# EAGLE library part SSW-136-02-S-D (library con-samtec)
THROUGH-HOLE .025" SQ POST SOCKET Source: Samtec SSW.pdf
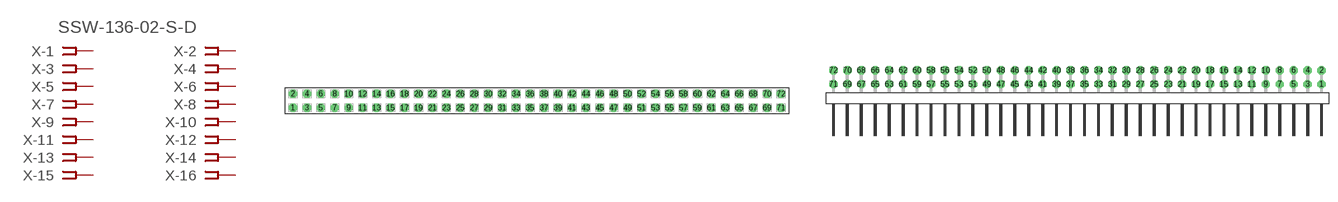
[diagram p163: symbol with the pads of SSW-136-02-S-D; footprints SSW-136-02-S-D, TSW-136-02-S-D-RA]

Designator prefix X; gates -1=FPINV -2=FPIN -3=FPIN -4=FPIN -5=FPIN -6=FPIN -7=FPIN -8=FPIN -9=FPIN -10=FPIN -11=FPIN -12=FPIN -13=FPIN -14=FPIN -15=FPIN -16=FPIN -17=FPIN -18=FPIN -19=FPIN -20=FPIN -21=FPIN -22=FPIN -23=FPIN -24=FPIN -25=FPIN -26=FPIN -27=FPIN -28=FPIN -29=FPIN -30=FPIN -31=FPIN -32=FPIN -33=FPIN -34=FPIN -35=FPIN -36=FPIN -37=FPIN -38=FPIN -39=FPIN -40=FPIN -41=FPIN -42=FPIN -43=FPIN -44=FPIN -45=FPIN -46=FPIN -47=FPIN -48=FPIN -49=FPIN -50=FPIN -51=FPIN -52=FPIN -53=FPIN -54=FPIN -55=FPIN -56=FPIN -57=FPIN -58=FPIN -59=FPIN -60=FPIN -61=FPIN -62=FPIN -63=FPIN -64=FPIN -65=FPIN -66=FPIN -67=FPIN -68=FPIN -69=FPIN -70=FPIN -71=FPIN -72=FPIN

## SSW-136-02-S-D (MPN: SSW-136-02-S-D; OC_FARNELL: unknown; OC_NEWARK: 11P9902)  [SSW-136-02-S-D]
1  -1:1  pas
2  -2:1  pas
3  -3:1  pas
4  -4:1  pas
5  -5:1  pas
6  -6:1  pas
7  -7:1  pas
8  -8:1  pas
9  -9:1  pas
10  -10:1  pas
11  -11:1  pas
12  -12:1  pas
13  -13:1  pas
14  -14:1  pas
15  -15:1  pas
16  -16:1  pas
17  -17:1  pas
18  -18:1  pas
19  -19:1  pas
20  -20:1  pas
21  -21:1  pas
22  -22:1  pas
23  -23:1  pas
24  -24:1  pas
25  -25:1  pas
26  -26:1  pas
27  -27:1  pas
28  -28:1  pas
29  -29:1  pas
30  -30:1  pas
31  -31:1  pas
32  -32:1  pas
33  -33:1  pas
34  -34:1  pas
35  -35:1  pas
36  -36:1  pas
37  -37:1  pas
38  -38:1  pas
39  -39:1  pas
40  -40:1  pas
41  -41:1  pas
42  -42:1  pas
43  -43:1  pas
44  -44:1  pas
45  -45:1  pas
46  -46:1  pas
47  -47:1  pas
48  -48:1  pas
49  -49:1  pas
50  -50:1  pas
51  -51:1  pas
52  -52:1  pas
53  -53:1  pas
54  -54:1  pas
55  -55:1  pas
56  -56:1  pas
57  -57:1  pas
58  -58:1  pas
59  -59:1  pas
60  -60:1  pas
61  -61:1  pas
62  -62:1  pas
63  -63:1  pas
64  -64:1  pas
65  -65:1  pas
66  -66:1  pas
67  -67:1  pas
68  -68:1  pas
69  -69:1  pas
70  -70:1  pas
71  -71:1  pas
72  -72:1  pas

## SSW-136-02-S-D-RA (MPN: SSW-136-02-S-D-RA; OC_FARNELL: unknown; OC_NEWARK: 11P9903)  [TSW-136-02-S-D-RA]
Pads as for SSW-136-02-S-D

## Footprint SSW-136-02-S-D (pad centres in mm)
THROUGH-HOLE .025" SQ POST SOCKET Source: Samtec SSW.pdf
drill 1 pad 1.5 octagon: 1 -44.45,-1.27; 2 -44.45,1.27; 3 -41.91,-1.27; 4 -41.91,1.27; 5 -39.37,-1.27; 6 -39.37,1.27; 7 -36.83,-1.27; 8 -36.83,1.27; 9 -34.29,-1.27; 10 -34.29,1.27; 11 -31.75,-1.27; 12 -31.75,1.27; 13 -29.21,-1.27; 14 -29.21,1.27; 15 -26.67,-1.27; 16 -26.67,1.27; 17 -24.13,-1.27; 18 -24.13,1.27; 19 -21.59,-1.27; 20 -21.59,1.27; 21 -19.05,-1.27; 22 -19.05,1.27; 23 -16.51,-1.27; 24 -16.51,1.27; 25 -13.97,-1.27; 26 -13.97,1.27; 27 -11.43,-1.27; 28 -11.43,1.27; 29 -8.89,-1.27; 30 -8.89,1.27; 31 -6.35,-1.27; 32 -6.35,1.27; 33 -3.81,-1.27; 34 -3.81,1.27; 35 -1.27,-1.27; 36 -1.27,1.27; 37 1.27,-1.27; 38 1.27,1.27; 39 3.81,-1.27; 40 3.81,1.27; 41 6.35,-1.27; 42 6.35,1.27; 43 8.89,-1.27; 44 8.89,1.27; 45 11.43,-1.27; 46 11.43,1.27; 47 13.97,-1.27; 48 13.97,1.27; 49 16.51,-1.27; 50 16.51,1.27; 51 19.05,-1.27; 52 19.05,1.27; 53 21.59,-1.27; 54 21.59,1.27; 55 24.13,-1.27; 56 24.13,1.27; 57 26.67,-1.27; 58 26.67,1.27; 59 29.21,-1.27; 60 29.21,1.27; 61 31.75,-1.27; 62 31.75,1.27; 63 34.29,-1.27; 64 34.29,1.27; 65 36.83,-1.27; 66 36.83,1.27; 67 39.37,-1.27; 68 39.37,1.27; 69 41.91,-1.27; 70 41.91,1.27; 71 44.45,-1.27; 72 44.45,1.27

## Footprint TSW-136-02-S-D-RA (pad centres in mm)
THROUGH-HOLE .025" SQ POST HEADER Source: Samtec TSW.pdf
drill 1 pad 1.5 octagon: 1 44.45,1.524; 2 44.45,4.064; 3 41.91,1.524; 4 41.91,4.064; 5 39.37,1.524; 6 39.37,4.064; 7 36.83,1.524; 8 36.83,4.064; 9 34.29,1.524; 10 34.29,4.064; 11 31.75,1.524; 12 31.75,4.064; 13 29.21,1.524; 14 29.21,4.064; 15 26.67,1.524; 16 26.67,4.064; 17 24.13,1.524; 18 24.13,4.064; 19 21.59,1.524; 20 21.59,4.064; 21 19.05,1.524; 22 19.05,4.064; 23 16.51,1.524; 24 16.51,4.064; 25 13.97,1.524; 26 13.97,4.064; 27 11.43,1.524; 28 11.43,4.064; 29 8.89,1.524; 30 8.89,4.064; 31 6.35,1.524; 32 6.35,4.064; 33 3.81,1.524; 34 3.81,4.064; 35 1.27,1.524; 36 1.27,4.064; 37 -1.27,1.524; 38 -1.27,4.064; 39 -3.81,1.524; 40 -3.81,4.064; 41 -6.35,1.524; 42 -6.35,4.064; 43 -8.89,1.524; 44 -8.89,4.064; 45 -11.43,1.524; 46 -11.43,4.064; 47 -13.97,1.524; 48 -13.97,4.064; 49 -16.51,1.524; 50 -16.51,4.064; 51 -19.05,1.524; 52 -19.05,4.064; 53 -21.59,1.524; 54 -21.59,4.064; 55 -24.13,1.524; 56 -24.13,4.064; 57 -26.67,1.524; 58 -26.67,4.064; 59 -29.21,1.524; 60 -29.21,4.064; 61 -31.75,1.524; 62 -31.75,4.064; 63 -34.29,1.524; 64 -34.29,4.064; 65 -36.83,1.524; 66 -36.83,4.064; 67 -39.37,1.524; 68 -39.37,4.064; 69 -41.91,1.524; 70 -41.91,4.064; 71 -44.45,1.524; 72 -44.45,4.064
